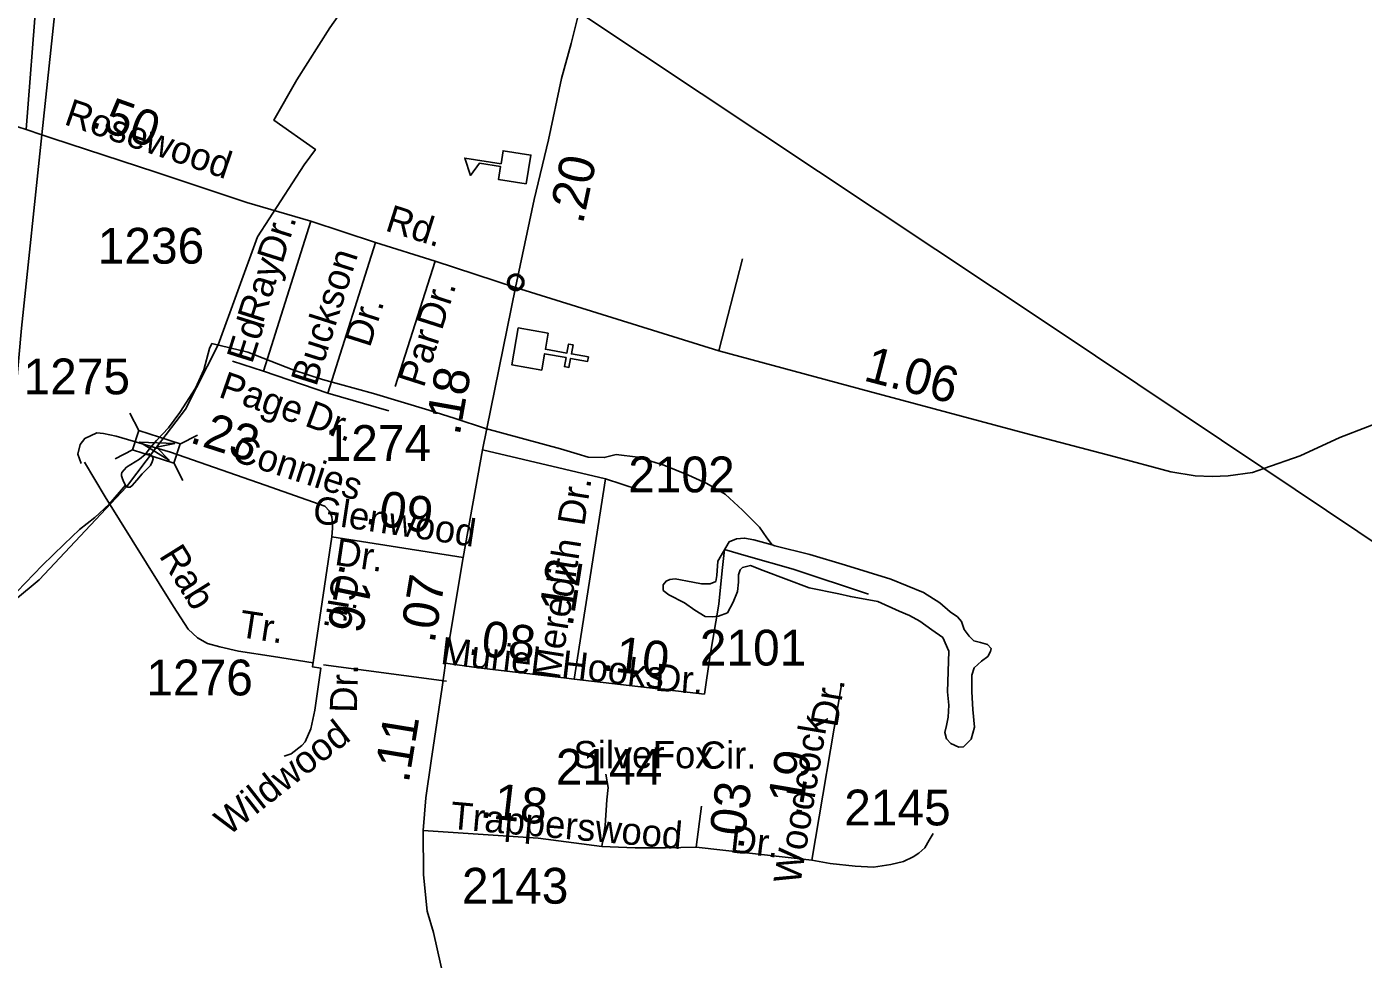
# Model space of a CAD drawing. Extents: x 2206922 to 2357709, y 510027 to 673830.
# Drawn here: x 2275145 to 2279814, y 604340 to 607597 of the extents above; entities that cross this region are included whole.
import ezdxf

# ---------------------------------------------------------------- set-up
doc = ezdxf.new("R2010")
doc.units = 0
for name, color, linetype in [('Exist Boundary Political Urban Extension UEB', 7, 'Continuous'), ('Exist Civil Demographics Community CELL', 7, 'Continuous'), ('Exist Cultural Church CELL', 7, 'Continuous'), ('Exist Cultural Educational Facility High CELL', 7, 'Continuous'), ('Exist Hydrographic Creek Single Shore', 7, 'Continuous'), ('Exist Hydrographic Misc Water Feature', 7, 'Continuous'), ('Exist Railroad Mainline', 7, 'Continuous'), ('Exist Road Non-System Type 51', 7, 'Continuous'), ('Exist Road Non-System Type 51 Label', 7, 'Continuous'), ('Exist Road Primary NC Attributed', 7, 'Continuous'), ('Exist Road Primary NC Mileage Hundredths English Label', 7, 'Continuous'), ('Exist Road Secondary Mileage Hundredths English Label', 7, 'Continuous'), ('Exist Road Secondary Structure Standard Bridge Attributed CELL', 7, 'Continuous'), ('Exist Road Secondary Structure Standard Bridge CELL', 7, 'Continuous'), ('Exist Road Secondary Type 51 Attributed', 7, 'Continuous'), ('Exist Road Secondary Type 51 Label', 7, 'Continuous'), ('Exist Road Secondary Type 51 Number Label', 7, 'Continuous'), ('Exist Utilities Electrical Transmission Line', 7, 'Continuous')]:
    doc.layers.add(name, color=color, linetype=linetype)

msp = doc.modelspace()

# ---------------------------------------------------------------- linework, layer by layer
at = {"layer": 'Exist Boundary Political Urban Extension UEB'}
msp.add_line((2275266.2, 608845.4), (2275143.8, 607237.3), dxfattribs=at)
at = {"layer": 'Exist Civil Demographics Community CELL'}
msp.add_lwpolyline([(2276830.1, 606708), (2276830.4, 606709.7), (2276830.9, 606711.7), (2276831.8, 606713.9), (2276832.7, 606715.6), (2276833.7, 606717.4), (2276834.9, 606718.9), (2276836.1, 606720.3), (2276837.5, 606721.7), (2276839.1, 606723.1), (2276840.8, 606724.2), (2276842.3, 606725), (2276843.8, 606725.8), (2276845.5, 606726.5), (2276847.2, 606727), (2276848.5, 606727.4), (2276850, 606727.6), (2276851.3, 606727.8), (2276853.2, 606727.9), (2276854.6, 606727.9), (2276856.3, 606727.8), (2276857.8, 606727.6), (2276859.3, 606727.3), (2276860.8, 606726.9), (2276862.4, 606726.3), (2276864.4, 606725.4), (2276866.3, 606724.3), (2276867.9, 606723.2), (2276869.4, 606722), (2276870.4, 606721.1), (2276871.7, 606719.7), (2276872.9, 606718.3), (2276873.8, 606716.9), (2276874.8, 606715.4), (2276875.5, 606713.8), (2276876.1, 606712.3), (2276876.6, 606710.7), (2276877, 606709.3), (2276877.3, 606707.5), (2276877.5, 606706.1), (2276877.6, 606704.2), (2276877.5, 606702.5), (2276877.4, 606700.7), (2276877.1, 606699.1), (2276876.6, 606697.2), (2276876, 606695.4), (2276875.3, 606693.9), (2276874.4, 606692), (2276873.3, 606690.4), (2276872.3, 606689), (2276871, 606687.5), (2276869.4, 606686), (2276867.9, 606684.8), (2276866.3, 606683.7), (2276865, 606682.9), (2276862.9, 606682), (2276860.8, 606681.1), (2276859, 606680.7), (2276856.9, 606680.3), (2276855.6, 606680.1), (2276854.2, 606680.1), (2276852.5, 606680.1), (2276851.2, 606680.2), (2276849.5, 606680.4), (2276847.7, 606680.8), (2276846.3, 606681.2), (2276844.7, 606681.8), (2276843.3, 606682.4), (2276842.1, 606683.1), (2276840.1, 606684.3), (2276838.4, 606685.6), (2276836.9, 606687), (2276835.5, 606688.5), (2276834.5, 606689.7), (2276833.6, 606690.9), (2276832.4, 606693.1), (2276831.8, 606694.2), (2276831.3, 606695.4), (2276830.5, 606697.9), (2276830.1, 606700.1), (2276829.9, 606701.6), (2276829.8, 606703.6), (2276829.7, 606705), (2276829.9, 606707)], close=True, dxfattribs=at)
msp.add_lwpolyline([(2276830.1, 606708), (2276830.4, 606709.7), (2276830.9, 606711.7), (2276831.8, 606713.9), (2276832.7, 606715.6), (2276833.7, 606717.4), (2276834.9, 606718.9), (2276836.1, 606720.3), (2276837.5, 606721.7), (2276839.1, 606723.1), (2276840.8, 606724.2), (2276842.3, 606725), (2276843.8, 606725.8), (2276845.5, 606726.5), (2276847.2, 606727), (2276848.5, 606727.4), (2276850, 606727.6), (2276851.3, 606727.8), (2276853.2, 606727.9), (2276854.6, 606727.9), (2276856.3, 606727.8), (2276857.8, 606727.6), (2276859.3, 606727.3), (2276860.8, 606726.9), (2276862.4, 606726.3), (2276864.4, 606725.4), (2276866.3, 606724.3), (2276867.9, 606723.2), (2276869.4, 606722), (2276870.4, 606721.1), (2276871.7, 606719.7), (2276872.9, 606718.3), (2276873.8, 606716.9), (2276874.8, 606715.4), (2276875.5, 606713.8), (2276876.1, 606712.3), (2276876.6, 606710.7), (2276877, 606709.3), (2276877.3, 606707.5), (2276877.5, 606706.1), (2276877.6, 606704.2), (2276877.5, 606702.5), (2276877.4, 606700.7), (2276877.1, 606699.1), (2276876.6, 606697.2), (2276876, 606695.4), (2276875.3, 606693.9), (2276874.4, 606692), (2276873.3, 606690.4), (2276872.3, 606689), (2276871, 606687.5), (2276869.4, 606686), (2276867.9, 606684.8), (2276866.3, 606683.7), (2276865, 606682.9), (2276862.9, 606682), (2276860.8, 606681.1), (2276859, 606680.7), (2276856.9, 606680.3), (2276855.6, 606680.1), (2276854.2, 606680.1), (2276852.5, 606680.1), (2276851.2, 606680.2), (2276849.5, 606680.4), (2276847.7, 606680.8), (2276846.3, 606681.2), (2276844.7, 606681.8), (2276843.3, 606682.4), (2276842.1, 606683.1), (2276840.1, 606684.3), (2276838.4, 606685.6), (2276836.9, 606687), (2276835.5, 606688.5), (2276834.5, 606689.7), (2276833.6, 606690.9), (2276832.4, 606693.1), (2276831.8, 606694.2), (2276831.3, 606695.4), (2276830.5, 606697.9), (2276830.1, 606700.1), (2276829.9, 606701.6), (2276829.8, 606703.6), (2276829.7, 606705), (2276829.9, 606707)], close=True, dxfattribs=at)
for centre, radius in [((2276853.7, 606704.2), 28.8), ((2276853.7, 606704.2), 28.8), ((2276853.6, 606704.3), 23.4), ((2276853.6, 606704.3), 23.4)]:
    msp.add_circle(centre, radius, dxfattribs=at)
at = {"layer": 'Exist Cultural Church CELL'}
msp.add_lwpolyline([(2276967.3, 606526.3), (2276957.4, 606470.3), (2277032.3, 606456.9), (2277038, 606488.4), (2277053.7, 606485.6), (2277048.1, 606454.1), (2277107.3, 606443.5), (2277104.5, 606427.8), (2277045.3, 606438.3), (2277039.6, 606406.8), (2277023.9, 606409.6), (2277029.5, 606441.1), (2276954.6, 606454.5), (2276944.3, 606397.7), (2276839.5, 606416.4), (2276862.5, 606545)], close=True, dxfattribs=at)
at = {"layer": 'Exist Cultural Educational Facility High CELL'}
msp.add_lwpolyline([(2276890.5, 607047.8), (2276793.8, 607063), (2276801, 607108.5), (2276726.8, 607120.2), (2276695.5, 607077.5), (2276675.5, 607138), (2276802.5, 607118), (2276809.6, 607163.4), (2276906.4, 607148.2)], close=True, dxfattribs=at)
at = {"layer": 'Exist Hydrographic Creek Single Shore'}
msp.add_lwpolyline([(2275482.5, 602914), (2275367.6, 603398.5), (2275023.5, 604563.1), (2274947.7, 604653.2), (2274904.6, 604854.2), (2274802.5, 605059.5), (2274800.7, 605269.5), (2274932.5, 605453.7), (2275188.6, 605665), (2275493.5, 605990.1), (2275598.7, 606128.4), (2275699.6, 606261.3), (2275813.6, 606485.4), (2275951.6, 606863), (2276114.1, 607114.1), (2276154, 607168.5), (2276008.9, 607270.2), (2276088.7, 607411.7), (2276204.8, 607593.2), (2276424.7, 607906.1)], dxfattribs=at)
at = {"layer": 'Exist Hydrographic Misc Water Feature'}
for points in [[(2275791.9, 606490.8), (2275783.7, 606472.6), (2275764.6, 606398.4), (2275735.1, 606334.3), (2275679.9, 606249.7), (2275640.3, 606195.7), (2275598.9, 606151.2), (2275577.4, 606126.9), (2275559.3, 606102.8)], [(2277749.3, 605787.5), (2277730.6, 605811.4), (2277704.8, 605849.3), (2277646.2, 605908.5), (2277585.7, 605963.8), (2277520.9, 606001.5), (2277456.9, 606030.6), (2277370.6, 606065.9), (2277280.3, 606092.9), (2277204.1, 606102.4), (2277162.9, 606092), (2277106.5, 606093.6), (2277068.5, 606104.9), (2277010.1, 606122.3), (2276748, 606193.8), (2276641.6, 606228.9), (2276549.5, 606257.8), (2276356.8, 606316), (2276178.8, 606364.3), (2276078.3, 606397.3), (2275917.6, 606460.1), (2275791.9, 606490.8)], [(2275490.2, 605996.1), (2275484.3, 606006.3), (2275479.8, 606017.9), (2275475.9, 606028.2), (2275476.1, 606033.9), (2275477.9, 606040.1), (2275494.1, 606058.3), (2275539.2, 606086.4), (2275559.3, 606102.8)], [(2275559.3, 606102.8), (2275573.3, 606104.8), (2275583.5, 606097.2), (2275587.4, 606087.3), (2275583.5, 606076.9), (2275577.6, 606064.8), (2275548.1, 606034.8), (2275529.8, 606012.8), (2275514, 605994.5), (2275506.2, 605988.4), (2275498.2, 605988.4), (2275492.1, 605990.1), (2275490.2, 605996.1)], [(2275490.2, 605996.1), (2275433.2, 605929.6), (2275383.4, 605883.2), (2275329.9, 605840.5), (2275276.6, 605790.2), (2275199.1, 605715.5), (2275112.1, 605624.8), (2275044.9, 605552.2), (2275001.6, 605493.8), (2274946, 605433.2), (2274876.7, 605366.7), (2274832.6, 605332.3), (2274795.1, 605308), (2274765.4, 605285.7), (2274754.3, 605223.7), (2274787.3, 605086.1), (2274824, 604994.6), (2274877.1, 604884.8), (2274944.2, 604773.7), (2274995, 604666.3), (2275015.5, 604618.6)], [(2277749.3, 605787.5), (2277684.9, 605804.8), (2277652.9, 605810.9), (2277624.8, 605808.2), (2277599.4, 605798.3), (2277559.4, 605729.7), (2277556.1, 605679.9), (2277552.4, 605659.8), (2277532.4, 605651.4), (2277502.6, 605651.5), (2277472.1, 605657.3), (2277410.3, 605668.6), (2277392.5, 605666.4), (2277378.6, 605660), (2277368.5, 605648.1), (2277369.1, 605628.2), (2277389, 605612.2), (2277443.2, 605585), (2277479.7, 605559.2), (2277515.5, 605537.6), (2277539.5, 605535.6), (2277561.5, 605537.9), (2277593.3, 605550.2), (2277613.3, 605586.5), (2277628.5, 605624.4), (2277632.2, 605656.6), (2277632.4, 605682.6), (2277637.8, 605700.4), (2277646, 605708.5), (2277673.8, 605714.9), (2277718.1, 605697.2), (2277878.5, 605637), (2277982.4, 605616), (2278022.6, 605606.4), (2278118.8, 605589), (2278193, 605555.9), (2278229.1, 605540.3), (2278265.4, 605520.7), (2278307.7, 605490.8), (2278346, 605463.5), (2278366.1, 605415.5), (2278361.6, 605273.4), (2278366.3, 605227.7), (2278364.5, 605185.8), (2278358.5, 605155.9), (2278352.8, 605131.6), (2278358.9, 605109.6), (2278373.3, 605093.6), (2278401.2, 605080.1), (2278417.4, 605082.1), (2278445, 605108.4), (2278456.7, 605150.8), (2278450, 605212.7), (2278447.5, 605274.3), (2278447.1, 605332.4), (2278454.7, 605358.3), (2278480.5, 605380.8), (2278502.5, 605397), (2278512.3, 605415), (2278514.3, 605424.8), (2278501.6, 605438.9), (2278477.8, 605446.5), (2278453.9, 605452.6), (2278437.9, 605468.4), (2278419.6, 605492.2), (2278411.4, 605519.8), (2278397.1, 605535.7), (2278370.8, 605553.5), (2278334.9, 605585.2), (2278278.3, 605620.6), (2278164.1, 605667.4), (2278005.6, 605716), (2277881.1, 605753), (2277759.1, 605783.5), (2277749.3, 605787.5)]]:
    msp.add_lwpolyline(points, dxfattribs=at)
at = {"layer": 'Exist Railroad Mainline'}
for points in [[(2279466.6, 606053.8), (2278731.4, 606546.2), (2277092, 607636.3), (2277075.8, 607647)], [(2283339.6, 602549.2), (2283180.3, 602730.4), (2283154.7, 602759.6), (2283013.2, 602922.3), (2282888.6, 603061.7), (2282825.4, 603132.4), (2282603.2, 603368.2), (2282433.6, 603560.6), (2282271.8, 603747), (2282045.7, 603992.7), (2281744.6, 604327.7), (2281506.4, 604579.3), (2281381.3, 604706), (2281286.5, 604793.1), (2281212.1, 604860.4), (2281147.6, 604913.8), (2281105.1, 604951.3), (2281042.9, 604994.7), (2280956.2, 605051.9), (2280885.9, 605103.3), (2279466.6, 606053.8)]]:
    msp.add_lwpolyline(points, dxfattribs=at)
at = {"layer": 'Exist Road Non-System Type 51'}
for p, q in [((2275972.4, 606394.3), (2276137.4, 606917.7)), ((2276364, 606843.7), (2276196.9, 606316.5)), ((2277645.7, 606785.9), (2277562.8, 606465.3)), ((2276572.4, 606777.7), (2276432.5, 606340.7)), ((2275972.4, 606394.3), (2275864.2, 606429.3)), ((2276196.9, 606316.5), (2275972.4, 606394.3)), ((2276410.9, 606255.7), (2276196.9, 606316.5)), ((2277167.3, 606017.7), (2276738.1, 606119.2)), ((2277281.5, 605980.8), (2277167.3, 606017.7)), ((2276181.9, 605368.8), (2276612.2, 605310.9))]:
    msp.add_line(p, q, dxfattribs=at)
for points in [[(2275347.3, 606075.9), (2275418.9, 605955.5), (2275658.2, 605571.7), (2275709, 605492.3), (2275741.6, 605462.5), (2275777.4, 605443), (2275819.5, 605431.5), (2275885.6, 605416), (2276007.7, 605397.3), (2276145.8, 605375.2)], [(2277513.2, 605265.6), (2277531.4, 605394.7), (2277562.9, 605580.2), (2277574.4, 605697.7), (2277582.7, 605770.6), (2277658.8, 605749), (2277822.6, 605702.7), (2278085.7, 605614.9)], [(2277154.5, 604733.2), (2277165.7, 604807.3), (2277172.4, 604897), (2277176.9, 604939.7), (2277167.9, 604986.8)], [(2277887.8, 604686.1), (2277951.7, 604674.6), (2278039.4, 604664.6), (2278103.1, 604661.4), (2278163.6, 604670.4), (2278208.5, 604681.6), (2278242.1, 604697.3), (2278262.3, 604710.8), (2278282.5, 604728.7), (2278298.2, 604755.7), (2278312.4, 604778.9)]]:
    msp.add_lwpolyline(points, dxfattribs=at)
at = {"layer": 'Exist Road Primary NC Attributed'}
msp.add_line((2276608.5, 605374.1), (2276669.5, 605743.5), dxfattribs=at)
for points in [[(2276853.2, 606686.5), (2276918.2, 606993), (2276968.2, 607201.3), (2277014.1, 607415.5), (2277047, 607537.8), (2277072, 607636.1), (2277075.8, 607647)], [(2276669.5, 605743.5), (2276738.1, 606119.2), (2276853.2, 606686.5)], [(2276530.4, 604789.3), (2276539.8, 604904.1), (2276558.7, 605033.1), (2276596.5, 605290.8), (2276608.5, 605374.1)], [(2277581.8, 603023.4), (2277464.3, 603136.8), (2277335.3, 603276.3), (2277209.7, 603394.1), (2277092.9, 603510.9), (2276952.2, 603650.9), (2276855.9, 603769.9), (2276817.4, 603820.6), (2276772.1, 603885.1), (2276728.9, 603958.7), (2276684.3, 604045.8), (2276649.2, 604128.2), (2276617.5, 604205.8), (2276566.5, 604432.9), (2276544.5, 604508), (2276531, 604634.3), (2276530.4, 604789.3)]]:
    msp.add_lwpolyline(points, dxfattribs=at)
at = {"layer": 'Exist Road Secondary Structure Standard Bridge Attributed CELL'}
msp.add_lwpolyline([(2275643.7, 606081.4), (2275540.5, 606146.4), (2275662.3, 606141.7), (2275598.7, 606128.4)], close=True, dxfattribs=at)
at = {"layer": 'Exist Road Secondary Structure Standard Bridge CELL'}
for p, q in [((2275505.9, 606247.7), (2275537.2, 606186.3)), ((2275680.8, 606139.3), (2275742.3, 606170.6)), ((2275453.9, 606087.8), (2275515.4, 606119.1)), ((2275659.5, 606073.7), (2275690.9, 606012.2))]:
    msp.add_line(p, q, dxfattribs=at)
msp.add_lwpolyline([(2275537.2, 606186.3), (2275680.9, 606139.6), (2275659.1, 606072.5), (2275515.4, 606119.1)], close=True, dxfattribs=at)
at = {"layer": 'Exist Road Secondary Type 51 Attributed'}
for p, q in [((2277058.2, 605318.4), (2277167.3, 606017.7)), ((2276669.5, 605743.5), (2276211, 605814.8)), ((2277058.2, 605318.4), (2277513.2, 605265.6)), ((2277484.1, 604731), (2277502.5, 604874.6))]:
    msp.add_line(p, q, dxfattribs=at)
for points in [[(2274125.2, 607595.5), (2275085.3, 607256.8), (2275143.8, 607237.3), (2275198.4, 607219.1), (2275233.3, 607207.4), (2275596.6, 607088.5), (2275914.8, 606983.4), (2276137.4, 606917.7), (2276364, 606843.7), (2276572.4, 606777.7), (2276853.2, 606686.5)], [(2276853.2, 606686.5), (2277562.8, 606465.3), (2278089, 606322.9), (2278636.5, 606176.6), (2278942.8, 606095.5), (2279142.5, 606042.1), (2279227.4, 606028.3), (2279286.7, 606026.3), (2279342.1, 606028.3), (2279427.1, 606040.1), (2279466.6, 606053.8)], [(2279466.6, 606053.8), (2279594.1, 606097.9), (2279732.9, 606162.5), (2279925.5, 606236.8), (2280094.5, 606305.7), (2280210.7, 606339.1), (2280315.1, 606353.1), (2280447.4, 606349.9), (2280602.4, 606333.8), (2280788.7, 606301.6), (2280891.8, 606275.6), (2281004.8, 606236.8), (2281166.2, 606172.2), (2281309.3, 606109.8), (2281514.8, 606024.7), (2281823.6, 605847.6), (2281942.5, 605770.1), (2281993.3, 605735.4), (2282098, 605645.8), (2282149.7, 605595.2)], [(2276211, 605814.8), (2276213, 605845.8), (2276213, 605862.1), (2276210.9, 605885), (2276203.5, 605905.3), (2276186.6, 605922.2), (2275978, 605995.4), (2275647.2, 606111.4), (2275516.7, 606149.4), (2275457.3, 606166.3), (2275414.1, 606175.7), (2275390.6, 606179), (2275347.9, 606158.2), (2275331.7, 606137.9), (2275323.6, 606104.2), (2275335, 606071.7)], [(2276211, 605814.8), (2276143.8, 605360.9), (2276173.2, 605356.2), (2276152.2, 605210), (2276144.8, 605176.9), (2276137.3, 605145.2), (2276118.4, 605099.3), (2276106.3, 605086.1), (2276068.7, 605057.1), (2276044.8, 605049)], [(2276608.5, 605374.1), (2276723.7, 605358), (2277021.8, 605322.7), (2277058.2, 605318.4)], [(2277887.8, 604686.1), (2277991.1, 605298.5)], [(2276530.4, 604789.3), (2276932.5, 604762.4), (2277154.5, 604733.2), (2277271.1, 604728.7), (2277376.5, 604728.7), (2277484.1, 604731)], [(2277484.1, 604731), (2277887.8, 604686.1)]]:
    msp.add_lwpolyline(points, dxfattribs=at)
at = {"layer": 'Exist Utilities Electrical Transmission Line'}
msp.add_line((2275362.6, 608781.5), (2275198.4, 607219.1), dxfattribs=at)
msp.add_lwpolyline([(2275198.4, 607219.1), (2275127.5, 606544.4), (2275091.3, 606142.3), (2275093.6, 606094.2), (2275080.2, 606050.1), (2275038.5, 605933.5)], dxfattribs=at)

# ---------------------------------------------------------------- texts
at = {"layer": 'Exist Road Non-System Type 51 Label'}
for s, rotation, p in [('Dr.', 72.5028, (2276038, 606765.9)), ('Ray', 72.5028, (2275970.1, 606557.2)), ('Buckson', 72.4136, (2276156.6, 606337.4)), ('Dr.', 72.2481, (2276595.2, 606533.2)), ('Dr.', 72.4136, (2276343.9, 606473.3)), ('Ed', 72.5028, (2275932.5, 606416.5)), ('Par', 72.2481, (2276532, 606333)), ('Page', 340.8868, (2275811.7, 606304.9)), ('Dr.', 339.6959, (2276112.2, 606204.6)), ('Rab', 301.9434, (2275605.5, 605749.3)), ('Tr.', 351.2938, (2275883.1, 605466.2))]:
    msp.add_text(s, height=95, rotation=rotation, dxfattribs=at).set_placement(p)
at = {"layer": 'Exist Road Primary NC Mileage Hundredths English Label'}
for s, rotation, p in [('.20', 77.9055, (2277087.9, 606904.4)), ('.18', 79.8884, (2276657.4, 606166.2)), ('.07', 80.6002, (2276569.9, 605440.8)), ('.11', 80.7289, (2276479.6, 604952.8))]:
    msp.add_text(s, height=125, rotation=rotation, dxfattribs=at).set_placement(p)
at = {"layer": 'Exist Road Secondary Mileage Hundredths English Label'}
for s, rotation, p in [('.50', 340.3397, (2275362.6, 607249.8)), ('1.06', 345.293, (2278064.9, 606362.2)), ('.23', 342.1295, (2275710.6, 606146.2)), ('.09', 351.3912, (2276324.3, 605861.5)), ('.16', 258.2758, (2276241.5, 605725.9)), ('.12', 81.1299, (2277051.8, 605498.5)), ('.08', 353.247, (2276683.8, 605404.9)), ('.10', 353.2822, (2277150.9, 605349.7)), ('.19', 80.4254, (2277849, 604829.7)), ('.18', 353.331, (2276725.7, 604836.4)), ('.03', 82.709, (2277648.3, 604720.9))]:
    msp.add_text(s, height=125, rotation=rotation, dxfattribs=at).set_placement(p)
at = {"layer": 'Exist Road Secondary Type 51 Label'}
for s, rotation, p in [('Rosewood', 341.2275, (2275272.2, 607257.1)), ('Rd.', 342.4279, (2276393.8, 606885.9)), ('Connies', 342.1295, (2275855.4, 606083.8)), ('Dr.', 81.1299, (2277092.8, 605850)), ('Glenwood', 351.3912, (2276140.4, 605865.7)), ('Dr.', 351.3912, (2276217.9, 605717.9)), ('Meredith', 81.1299, (2277006.9, 605313)), ('Cir.', 260.6221, (2276215, 605691.9)), ('Muriel', 353.247, (2276588.2, 605372)), ('Hooks', 353.2822, (2277010, 605325.4)), ('Dr.', 88.7276, (2276298.8, 605200.1)), ('Dr.', 355.7983, (2277337.4, 605278)), ('Dr.', 80.5422, (2277976.4, 605147.2)), ('Woodcock', 80.5422, (2277847.2, 604597.9)), ('Wildwood', 38.0875, (2275849.5, 604768.4)), ('Trapperswood', 354.9319, (2276622.2, 604796.1)), ('Dr.', 353.5066, (2277599.8, 604713.6))]:
    msp.add_text(s, height=95, rotation=rotation, dxfattribs=at).set_placement(p)
for s, p in [('Silver', (2277055.6, 605007.3)), ('Fox', (2277332.6, 605007.1)), ('Cir.', (2277496.7, 605005.6))]:
    msp.add_text(s, height=95, dxfattribs=at).set_placement(p)
at = {"layer": 'Exist Road Secondary Type 51 Number Label'}
for s, p in [('1236', (2275393.6, 606769.3)), ('1275', (2275134.3, 606312.9)), ('1274', (2276186.1, 606080.4)), ('2102', (2277246.8, 605970.7)), ('2101', (2277496.9, 605365.7)), ('1276', (2275563.5, 605261.4)), ('2144', (2276993.6, 604949.6)), ('2145', (2278001.2, 604807.4)), ('2143', (2276665.7, 604534.1))]:
    msp.add_text(s, height=125, dxfattribs=at).set_placement(p)

doc.saveas('drawing.dxf')
